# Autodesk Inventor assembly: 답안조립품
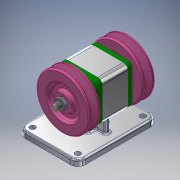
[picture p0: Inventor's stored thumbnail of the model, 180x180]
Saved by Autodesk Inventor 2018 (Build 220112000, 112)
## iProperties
Created: 2020-11
Part Number: 답안조립품
Material: 일반
Document SubType Name: Assembly
Designer: USER
Author: USER
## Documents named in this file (10)
- C:\Users\USER\Desktop\701106V1043\답안조립품.iam
- C:\Users\USER\Desktop\701106V1043\본체.ipt
- C:\Users\USER\Desktop\701106V1043\V-벨트풀리.ipt
- C:\Users\USER\Desktop\701106V1043\너트 M10x1.ipt
- C:\Users\USER\Desktop\701106V1043\베어링 6004.ipt
- C:\Users\USER\Desktop\701106V1043\볼트 M4.ipt
- C:\Users\USER\Desktop\701106V1043\오일 실 17 30 5.ipt
- C:\Users\USER\Desktop\701106V1043\축.ipt
- C:\Users\USER\Desktop\701106V1043\커버.ipt
- C:\Users\USER\Desktop\701106V1043\키 5 x 5 x 12.ipt
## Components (2 placed, 1 different names)
1. V-벨트풀리:1 — 각도:3
2. V-벨트풀리:2 — 각도:4
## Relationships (2: Angle 2)
- 각도:3 [Angle]: V-벨트풀리:1
- 각도:4 [Angle]: V-벨트풀리:2
